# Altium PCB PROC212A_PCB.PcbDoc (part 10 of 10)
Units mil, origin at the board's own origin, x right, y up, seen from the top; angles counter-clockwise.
Board outline 3032.48 x 3598.78 mil, 4 copper layers (Top Layer, L2_GND1, L3_PWR1, Bottom Layer), stack 60.58 mil thick; 432 components, 310 nets, 7775 pads, 1236 vias.
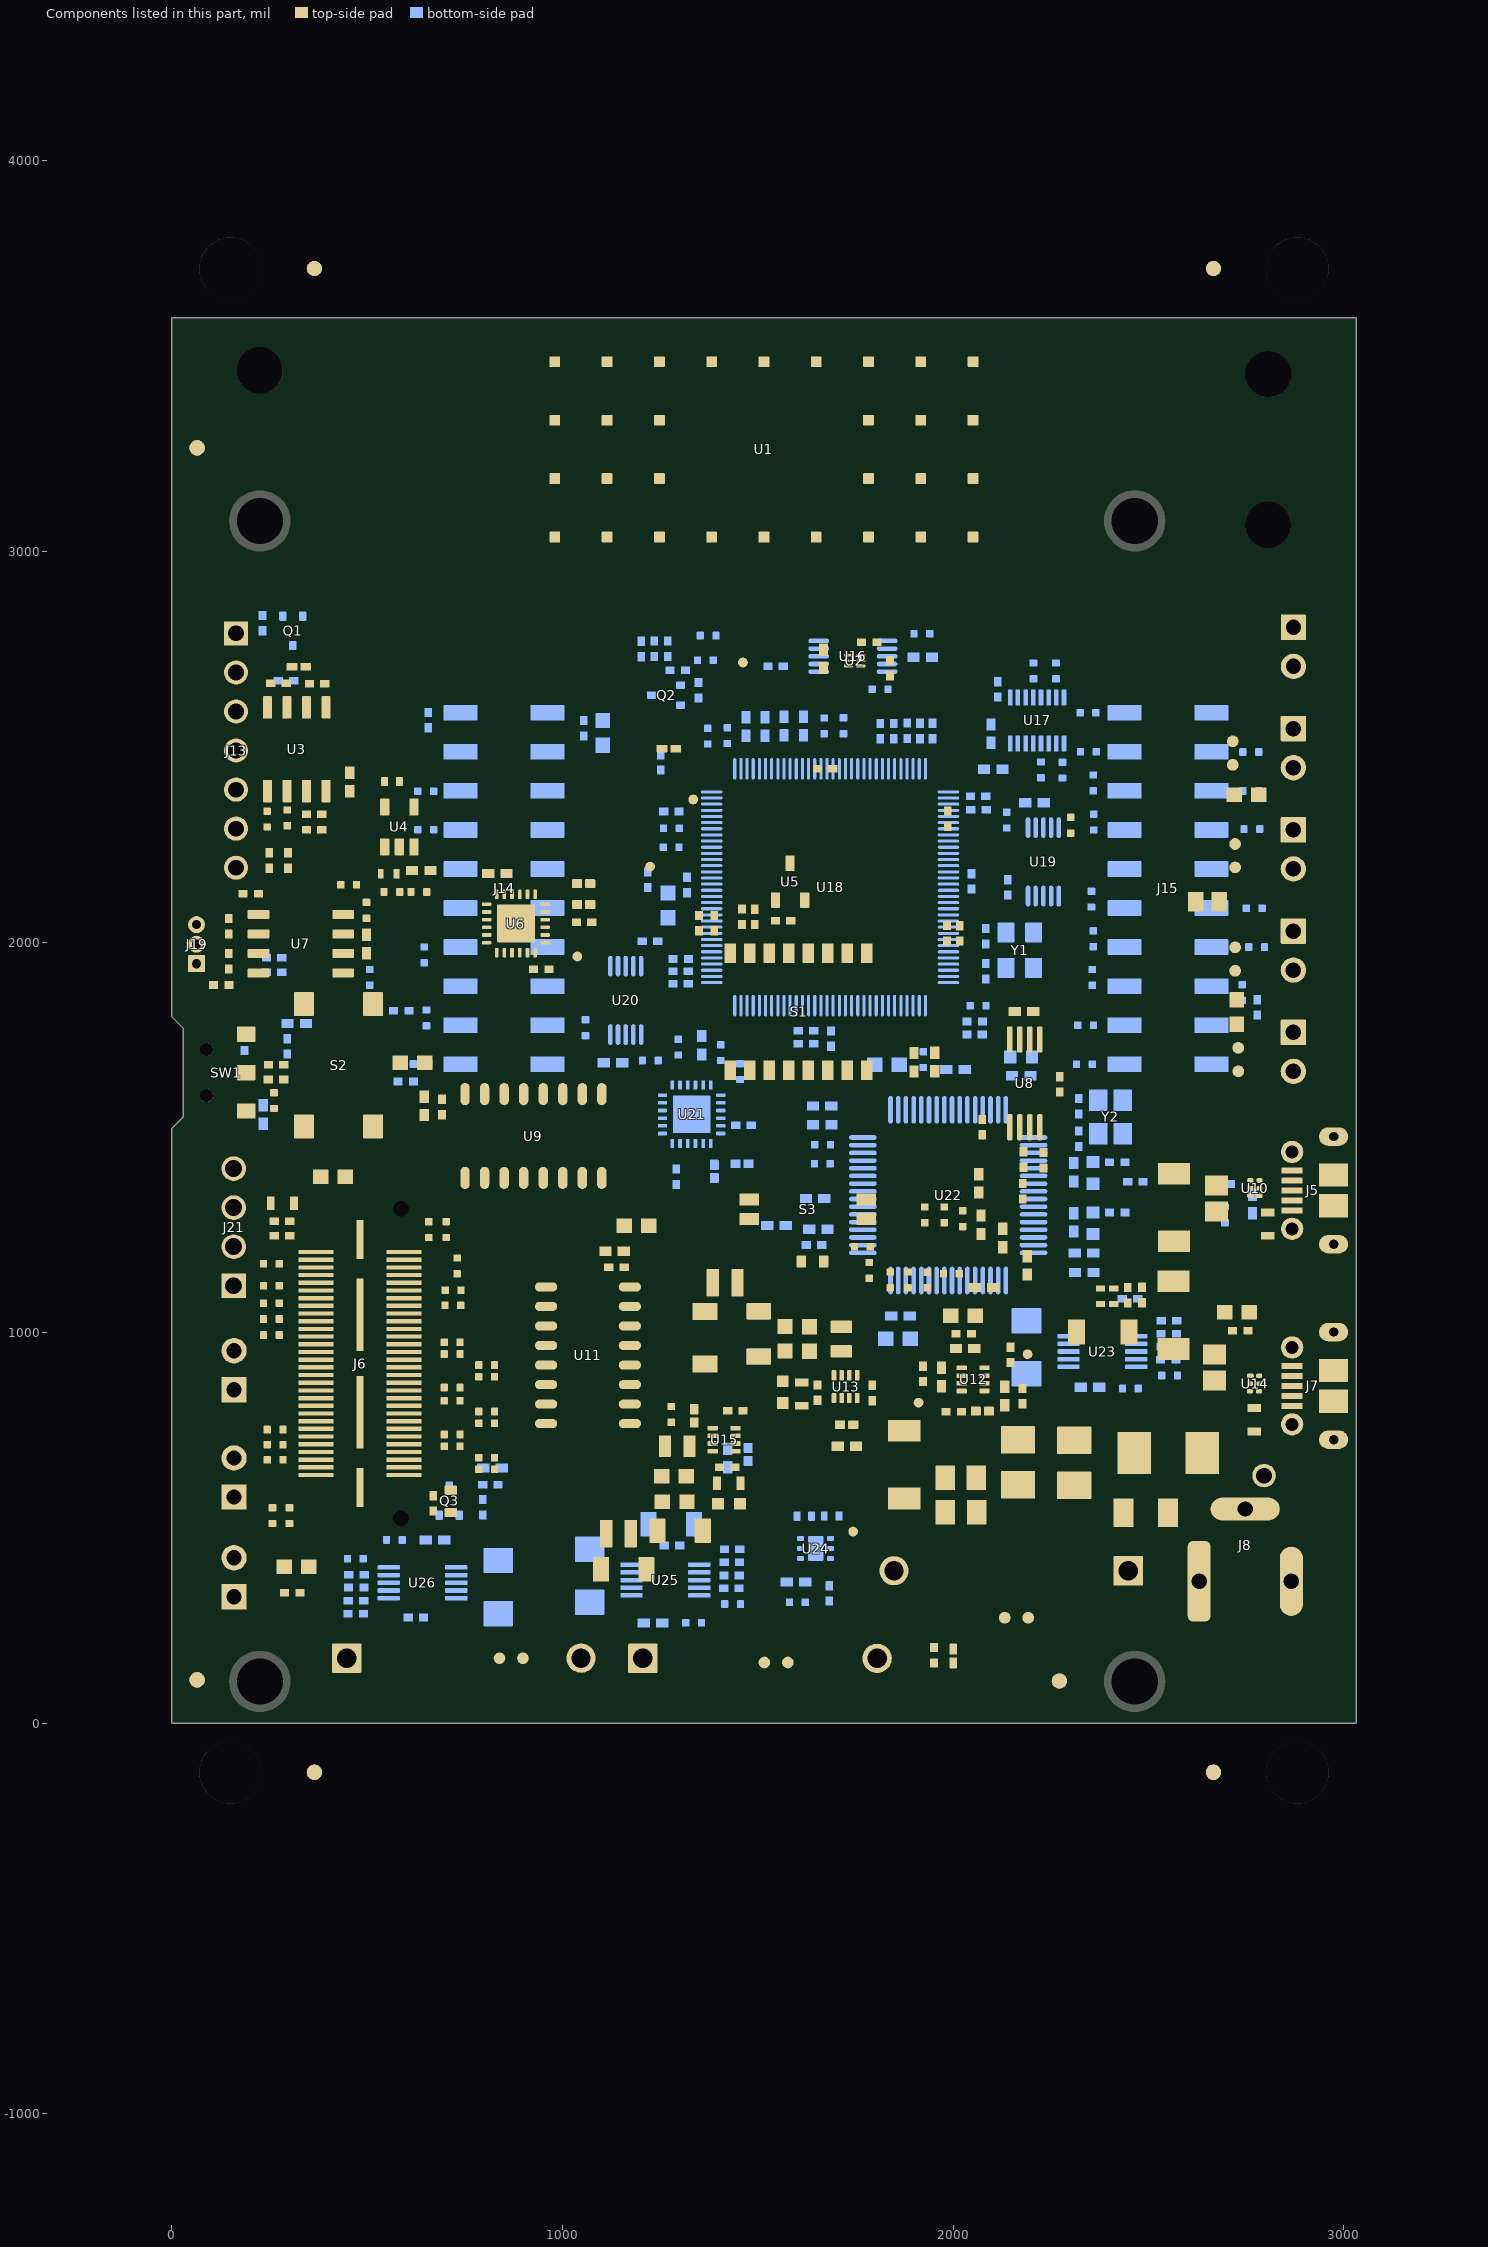
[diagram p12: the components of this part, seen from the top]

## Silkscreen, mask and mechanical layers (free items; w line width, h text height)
Top Overlay:
  circle w15: c1435.74,1342.41 r1
  circle w15: c1518.68,2068.65 r1
  circle w15: c2796.02,1333.86 r1
  circle w15: c2742.02,900.86 r1
  circle w15: c1783.02,2679.86 r1
  circle w15: c946.02,1161.86 r1
  circle w15: c706.02,1403.86 r1
  circle w15: c441.02,2599.86 r1
  circle w15: c555.14,1887.52 r3.1
  circle w1.51: c2325.05,2100.75 r4.71
  circle w1.51: c2325.05,2100.75 r4.71
  lines w0.38: 2318.02,2094.77 2273.52,2079.71 2318.02,2094.77 ; 2318.02,2094.77 2276.32,2074.11 2318.02,2094.77
  lines w0.76: 2315.22,2093.56 2310.14,2091.82 2315.22,2093.56 ; 2315.22,2093.56 2309.84,2091.14 2315.22,2093.56
  lines w1.51: 2309.84,2091.37 2274.5,2079.34 2309.84,2091.37 ; 2309.84,2091.37 2275.94,2074.87 2309.84,2091.37
  lines w3.03: 2280.03,2078.12 2277,2079.18 2280.03,2078.12 ; 2280.03,2078.12 2273.14,2075.63 2280.03,2078.12 ; 2202.83,2107.64 2207,2109.76 2202.83,2107.64 ; 2275.79,2077.44 2297.89,2086.37 2275.79,2077.44
  lines w6.81: 2174.23,2082.06 2178.39,2086.3 ; 2174.23,2082.06 2178.39,2086.3 ; 2174.23,2082.06 2167.87,2075.02 2174.23,2082.06 ; 2178.39,2086.3 2182.17,2089.93 ; 2178.39,2086.3 2182.17,2089.93 ; 2182.17,2089.93 2184.14,2091.82 ; 2182.17,2089.93 2184.14,2091.82 ; 2184.14,2091.82 2188.68,2095.45 ; 2184.14,2091.82 2188.68,2095.45 ; 2188.68,2095.45 2192.92,2098.94 ; 2188.68,2095.45 2192.92,2098.94 ; 2192.92,2098.94 2194.59,2100.07 ; 2192.92,2098.94 2194.59,2100.07 ; 2194.59,2100.07 2196.55,2101.28 ; 2194.59,2100.07 2196.55,2101.28 ; 2196.55,2101.28 2199.66,2103.25 2196.55,2101.28 ; 2203.59,2105.97 2196.25,2101.28 2203.59,2105.97 ; 2203.59,2105.97 2195.95,2101.21 2203.59,2105.97 ; 2209.04,2082.74 ccw(c2213.22,2079.56) 2216.53,2075.48 ; 2209.04,2082.74 ccw(c2213.22,2079.56) 2216.53,2075.48 ; 2209.04,2082.74 2223.8,2102.11 ; 2209.04,2082.74 2223.8,2102.11 ; 2212.29,2110.21 2216.15,2111.8 ; 2212.29,2110.21 2216.15,2111.8 ; 2212.29,2110.21 2207.3,2107.79 2212.29,2110.21 ; 2216.15,2111.8 cw(c2219.57,2104.52) 2223.57,2111.5 ; 2216.15,2111.8 cw(c2219.57,2104.52) 2223.57,2111.5 ; 2216.53,2075.48 cw(c2325.44,1885.68) 2261.41,2094.92 ; 2216.53,2075.48 cw(c2325.44,1885.68) 2261.41,2094.92 ; 2223.57,2111.5 cw(c2221.9,2108.59) 2225.16,2109.38 ; 2223.57,2111.5 cw(c2221.9,2108.59) 2225.16,2109.38 ; 2223.8,2102.11 ccw(c2216.39,2107.26) 2225.16,2109.38 ; 2223.8,2102.11 ccw(c2216.39,2107.26) 2225.16,2109.38 ; 2261.41,2094.92 cw(c2262.16,2089.46) 2267.54,2090.69 ; 2261.41,2094.92 cw(c2262.16,2089.46) 2267.54,2090.69 ; 2267.54,2090.69 cw(c2246.21,2085.81) 2267.77,2082.06 ; 2267.54,2090.69 cw(c2246.21,2085.81) 2267.77,2082.06 ; 2267.77,2082.06 ccw(c2272.69,2081.2) 2274.27,2076.46 cw(c2272.69,2081.2) 2267.77,2082.06 ; 2198.45,2102.42 2201.25,2104.31 2198.45,2102.42 ; 2199.88,2103.63 2205.26,2106.58 2199.88,2103.63
  lines w10: 2654.31,1702.09 2584.31,1702.09 2584.31,1943.09 2654.31,1943.09 ; 2654.31,1960.09 2584.31,1960.09 2584.31,2214.09 2654.31,2214.09 ; 2655.31,2231.09 2585.31,2231.09 2585.31,2483.09 2655.31,2483.09 ; 2900.09,2237.09 2970.09,2237.09 2970.09,2482.09 ; 2900.09,2483.09 2968.09,2483.09 ; 2901.09,1982.09 2971.09,1982.09 2971.09,2219.09 ; 2901.09,2220.09 2969.09,2220.09 ; 2901.31,1964.09 2971.31,1964.09 2971.31,1694.09 2909.31,1694.09
  text "RESET_LED" at 306.31,2746.09 h30
  text "PMIC_CLK_OUT" at 1149.02,2699.86 h25
  text "PROC212 REV. A" at 607.02,2633.86 h60
  text "VCC_MOD_3V3" at 2601.31,2548.09 h20
  text "PRESENCE_LED" at 854.02,2478.86 h30
  text "TEXAS" at 1450.6,2428.69 h25
  text "INSTRUMENTS" at 1405.15,2385.87 h25
  text "XDS_UART_RX" at 1255.69,2317.03 h20
  text "VCC_MOD" at 2953.31,2282.09 h25 r90
  text "XDS_UART_TX" at 1280.79,2194.46 h20
  text "R" at 2323.57,2098.67 h4.54
  text "7. FTDI_RS232" at 1683.77,2031.9 h20 r90
  text "6. FTDI_SPI" at 1714.94,2031.9 h20 r90
  text "5. XDS_RS232" at 1745.29,2031.9 h20 r90
  text "4. XDS_JTAG" at 1775.64,2031.9 h20 r90
  text "3. I2C" at 1808.44,2031.9 h20 r90
  text "2. LVDS" at 1842.07,2031.9 h20 r90
  text "1. FLASH/FUNCT MODE" at 1878.72,2031.9 h20 r90
  text "MISTRAL" at 2147.7,2018.27 h41.62
  text "VCC_1V8" at 2953.31,2015.09 h25 r90
  text "HOST_CLK_REQ" at 1026.33,1916.65 h20
  text "Func_MODE" at 50.89,1822.6 h27
  text "RESET_SW" at 567.31,1790.09 h30
  text "MUX_CTRL" at 1310.38,1736.41 h20 r90
  text "VCC_IO_MOD" at 2953.31,1713.09 h25 r90
  text "to be closed for Module power-up." at 2533.31,1634.09 h25 r90
  text "VCC_MODULE and VCC_IO_MOD jumpers/solder blobs" at 2475.31,1633.09 h25 r90
  text "VCC_IO_3V3" at 2629.31,1614.09 h20
  text "FTDI USB" at 2778.31,1545.09 h30
  text "Flash MODE" at 45.85,1489.23 h27
  text "SOP0 Switch" at 41.77,1453.57 h27
  text "DCA_LP_JTAG" at 1641.17,1415.02 h20 r90
  text "DCA_LP_SPI/" at 1530.18,1412.98 h20 r90
  text "CAN_FD_RX" at 1561.75,1412.98 h20 r90
  text "DEBUG MODE" at 1801.39,1412.05 h20 r90
  text "DCA_FTDI_SPI" at 1689.71,1409.55 h20 r90
  text "MOD_WU,GPIO/" at 1730.35,1407.12 h20 r90
  text "CAN_FD_TX" at 1766.35,1407.12 h20 r90
  text "FT_DCA_RS232" at 1594.68,1404.77 h20 r90
  text "DCA_LP_RS232" at 1488.02,1402.71 h20 r90
  text "I2C_SWITCH" at 1390.1,1212.7 h20 r90
  text "FTDI" at 1601,1128.84 h20
  text "XDS110 USB" at 2719.31,1098.09 h30
  text "SUSPEND" at 1565.48,1097.09 h20
  text "GND" at 2838.31,614.09 h30
  text "VCC_3V3" at 1644.02,515.86 h25
  text "P_GOOD" at 759.9,485.9 h20
  text "VCC_5V curr meas point" at 1862.31,452.09 h25
  text "DCA_CONN" at 499.96,447.49 h25
  text "VCC_5V" at 1970.8,311.96 h25
  text "3V3_MODULE curr meas point" at 1226.31,274.09 h25
  text "3V3_IO curr meas point" at 510.31,271.09 h25
  text "5V_SNS" at 2231.31,255.09 h25
  text "DC Jack" at 2757.31,129.09 h30
  text "5V_LED" at 1926.31,96.09 h25
  text "VCC_IO_3V3" at 877.31,67.09 h25
  text "3V3_MODULE_SNS" at 1152.31,67.09 h25
  text "VCC_MOD_3V3" at 1568.31,67.09 h25
  text "3V3_IO_SNS" at 585.31,65.09 h25
  text ".Layer_Name" at -379.69,-686.91 h60
Bottom Overlay:
  circle w10: c2483.02,1602.86 r3.16
  circle w10: c1712.02,478.86 r3.16
  circle w15: c1640.1,2653.48 r3.1
  circle w15: c1106.09,1979.63 r3.1
  circle w15: c2143.74,2668.12 r3.1
  circle w15: c2309.05,2115.36 r3.1
  circle w15: c1196.15,2629.78 r3.1
  rectangle: 550.57,1016.4 1239,1114.63
  lines w6: 2811.31,2130.09 2811.31,2152.09 2826.31,2167.09 ; 2812.31,1829.09 2812.31,1811.09 2826.31,1797.09 ; 2813.31,2344.09 2813.31,2326.09 2827.31,2312.09 ; 2814.4,2093.91 2814.4,2075.91 2828.4,2061.91 ; 2816.31,2390.09 2816.31,2412.09 2831.31,2427.09 ; 2819.76,1871.34 2819.76,1893.34 2834.76,1908.34
  lines w10: 550.57,1116.54 1376.75,1116.54 ; 550.57,1116.68 550.57,1016.54 1376.75,1016.54 1376.75,1116.68 ; 1238.45,1016.4 1238.45,1114.63
  text "SPI_CONN" at 198.31,2907.09 h25
  text "GND" at 2814.02,2784.86 h20
  text "LP/BP_CONN" at 2671.18,2705.83 h25
  text "GND" at 2816.02,2698.86 h20
  text "MOSI" at 307.18,2697.09 h25
  text "LP/BP_CONN" at 957.02,2697.15 h25
  text "3V3" at 720.31,2633.09 h35
  text "5V" at 1021.31,2633.09 h35
  text "GND" at 2748.22,2627.02 h35
  text "MISO" at 311.35,2568.09 h25
  text "3V3_MOD" at 2830.22,2533.28 h20
  text "CS" at 265.53,2475.09 h25
  text "CLK" at 290.52,2374.2 h25
  text "VCC_MOD" at 2937.14,2359.93 h20
  text "HOST_INTR" at 436.31,2269.09 h25
  text "GND" at 290.52,2170.2 h25
  text "VCC_1V8" at 2944.31,2102.09 h20
  text "CAN_HEADER" at 392.84,2083.73 h25
  text "CANL" at 194.04,2032.61 h25
  text "GND" at 177.24,1981.01 h25
  text "CANH" at 198.44,1929.41 h25
  text "VCC_MOD_IO" at 2991.52,1842.8 h20
  text "3V3_IO_PWR" at 2899.31,1594.09 h20
  text "GND" at 258.64,1405.37 h20
  text "TX" at 236.54,1308.13 h20
  text "RS232_CONN" at 498.34,1270.22 h25
  text "RX" at 244.28,1210.9 h20
  text "FY25-26/00546000101" at 1274.31,1159.09 h28
  text "VCC_IO_MOD" at 395.65,1108.14 h20
  text "SL#" at 1365.15,1038.2 h70
  text "MCU_5V_HDR" at 414.08,831.33 h20
  text "GND" at 2919.63,610.28 h30
  text "VPP_LDO" at 359.65,604.45 h20
  text "MCU_3V3" at 288.59,463.77 h20
  text ".Layer_Name" at -426.69,-683.91 h60
Top Paste:
  text ".Layer_Name" at -544.88,-674.55 h60
Bottom Paste:
  text ".Layer_Name" at -544.88,-674.55 h60
Top Solder:
  text ".Layer_Name" at -374.69,-678.91 h60
  text ".Layer_Name" at -397.69,-681.91 h60
Bottom Solder:
  text ".Layer_Name" at -404.69,-686.91 h60
Drill Guide:
  text ".Layer_Name" at 213.27,-699.88 h60
M1 Board Outline:
  lines w6: 0.02,-0.02 0.02,-275.73 3032.46,-275.73 3032.46,0 ; 0,3598.78 3032.51,3598.78 ; 0,3598.78 0,3874.51 3032.51,3874.51 3032.51,3598.78 ; 0,3598.78 0,1808.43 29.41,1779.02 29.41,1552.81 0,1523.4 0,0 3032.46,0 ; 3032.48,0 3032.48,3598.78 ; 3031.47,1559.07 3031.49,1559.07
  text ".Layer_Name" at -480.55,-740.88 h40
M3 3D STEP Top:
  text ".Layer_Name" at -544.88,-674.55 h60
M4 3D STEP Bottom:
  text ".Layer_Name" at -544.88,-674.55 h60
M5 Assembly Top:
  circle w6: c2718.02,2482.86 r60
  circle w6: c2721.39,2217.76 r60
  circle w6: c2723.78,1953.96 r60
  circle w6: c2730.36,1697.34 r60
  circle w6: c870.44,164.1 r60
  circle w6: c1549.02,155.86 r60
  circle w6: c2162.02,268.86 r60
  circle w6: c2796.2,634.06 r39.69
  circle w6: c1744.12,490.77 r18.56
  circle w6: c1911.68,820.76 r18.56
  circle w6: c2190.81,944.83 r18.56
  circle w6: c1462.02,2715.86 r18.56
  circle w6: c1334.73,2365.09 r18.56
  circle w6: c1224.1,2193.24 r18.56
  circle w6: c1038.08,1963.33 r18.56
  lines w10: -1386.45,-990.71 5213.55,-990.71 ; -1386.45,-787.38 5215.55,-787.38 ; -1386.45,-584.04 -1386.45,-1194.04 2618.55,-1194.04 5215.55,-1194.04 5215.55,-584.04 -1385.95,-584.04 -1385.95,-1194.04 189.55,-1194.04 ; 1078.55,-1194.04 1078.55,-584.04 ; 2345.55,-787.38 2345.55,-584.04 ; 3185.55,-787.38 3185.55,-584.04 ; 3807.55,-1200.54 3807.55,-997.71
  text "COMPONENTS MARKED 'DNP' SHOULD NOT BE POPULATED." at -689.69,4171.09 h60
  text "ASSEMBLY VARIANT:" at -221.21,4053.92 h60
  text ".VariantName" at 814.79,4053.92 h60
  text "TP1" at 1492.29,2709.08 h24
  text "J1" at 2594.21,2495.66 h24
  text "TP2" at 1365.01,2358.31 h24
  text "J2" at 2605.91,2250.38 h24
  text "TP3" at 1203.15,2222.38 h24
  text "J3" at 2596.91,1975.38 h24
  text "TP4" at 1068.35,1956.55 h20
  text "J4" at 2602.91,1666.38 h24
  text "TP5" at 2220.09,937.05 h14
  text "TP6" at 1882.5,807.76 h16 r90
  text "TP7" at 2851.24,653.63 h20
  text "TP8" at 1774.39,483.99 h24
  text "J11" at 1523.94,235.61 h24
  text "J10" at 923.14,230.22 h24
  text "J9" at 2144.91,152.37 h24
  text "PCB VIEWED FROM TOP SIDE" at -1280.46,-526.57 h60
  text "BOARD #:" at 1196.04,-526.57 h60
  text ".PRJ_Number" at 1741.54,-526.57 h60
  text "REV:" at 2586.04,-526.57 h60
  text ".PCB_Rev" at 2877.54,-526.57 h60
  text "SVN REV:" at 3424.04,-526.57 h60
  text ".VersionControl_RevNumber" at 3930.04,-526.57 h60
  text "Assembly Layer Top" at -513.95,-667.54 h60
  text "TID #:" at 1196.04,-729.91 h60
  text ".TID" at 1741.54,-729.91 h60
  text "PLOT NAME =" at -1280.46,-935.24 h60
  text ".plot_File_Name" at -474.96,-935.24 h60
  text ".Print_Date" at 2067.54,-935.24 h60
  text ".Print_Time" at 2796.54,-935.24 h60
  text "TEXAS INSTRUMENTS" at 4061.04,-935.24 h60
  text "GENERATED    :" at 1201.02,-936.14 h60
M6 Assembly Bottom:
  circle w4: c1437.91,2242.94 r15
  lines w10: -1384.46,-788.24 5217.54,-788.24 ; -1382.46,-991.57 5217.54,-991.57 ; 23.54,-1201.41 23.54,-998.57 ; 645.54,-788.24 645.54,-584.91 ; 1485.54,-788.24 1485.54,-584.91 ; 2752.54,-1194.91 2752.54,-584.91 ; 3641.54,-1194.91 5217.04,-1194.91 5217.04,-584.91 -1384.46,-584.91 -1384.46,-1194.91 1212.54,-1194.91 5217.54,-1194.91 5217.54,-584.91
  text "COMPONENTS MARKED 'DNP' SHOULD NOT BE POPULATED." at 5201.02,-357.14 h60
  text ".VariantName" at 4170.61,-477.86 h60
  text "ASSEMBLY VARIANT:" at 5209.61,-477.86 h60
  text ".VersionControl_RevNumber" at -56.46,-717.07 h60
  text "SVN REV:" at 449.54,-717.07 h60
  text ".PCB_Rev" at 996.04,-717.07 h60
  text "REV:" at 1287.54,-717.07 h60
  text ".PRJ_Number" at 2132.04,-717.07 h60
  text "BOARD #:" at 2677.54,-717.07 h60
  text "PCB VIEWED FROM BOTTOM SIDE" at 5154.04,-717.07 h60
  text "Assembly Bottom Layer" at 4793.04,-905.91 h60
  text ".TID" at 2132.04,-920.41 h60
  text "TID #:" at 2677.54,-920.41 h60
  text "GENERATED    :" at 2708.02,-1116.91 h60
  text "TEXAS INSTRUMENTS" at -187.46,-1125.74 h60
  text ".Print_Time" at 1077.04,-1125.74 h60
  text ".Print_Date" at 1806.04,-1125.74 h60
  text ".plot_File_Name" at 4348.54,-1125.74 h60
  text "PLOT NAME =" at 5154.04,-1125.74 h60
M10 Fab Notes:
  drawing of 356 lines, arcs and shapes, not listed
  text "1" at -312.13,8207.59 h70
  text "2" at 2183.54,8207.59 h70
  text "3" at 4672.88,8207.59 h70
  text "4" at 7179.55,8207.59 h70
  text "5" at 9678.54,8207.59 h70
  text "6" at 12183.54,8207.59 h70
  text "A" at -1468.46,7064.59 h70
  text "A" at 13331.54,7064.59 h70
  text "DESIGN INFORMATION" at 11330.05,6527.27 h60
  text "4.0" at 11724.53,6397.87 h60
  text "MIN. TRACK WIDTH:" at 10685.49,6395.14 h60
  text "MIL" at 11936.49,6395.14 h60
  text "4.5" at 11721.99,6278.49 h60
  text "MIN. CLEARANCE:" at 10685.49,6271.02 h60
  text "MIL" at 11936.49,6271.02 h60
  text "MIN. VIA PAD SIZE:" at 10685.49,6146.89 h60
  text "18" at 11708.18,6139.52 h60
  text "MIL" at 11959.04,6138.09 h60
  text "EXTERNAL" at 12206.64,6019.58 h60
  text "0.127mm (5.0MIL)" at 11380.5,6016.99 h60
  text "MINIMUM ANNULAR RING" at 10356.26,6008.77 h60
  text "PER" at 10556.26,5898.64 h60
  text "IPC-D-275 CLASS 2 LEVEL C" at 10776.26,5898.64 h60
  text "45" at 7428.01,5823.91 h80
  text "MIL, HOLES" at 12264.49,5798.16 h60
  text "+/-" at 11872.04,5789.58 h60
  text "+/-" at 12726.04,5789.58 h60
  text "REGISTRATION TOLERANCES:" at 10356.26,5788.51 h60
  text "METAL" at 11556.04,5788.51 h60
  text "2" at 12132.24,5788.52 h60
  text "3" at 12965.24,5788.52 h60
  text "MIL" at 13081.49,5788.51 h60
  text "HOLE SIZE TOLERANCE (UNLESS OTHERWISE SPECIFIED):" at 10356.26,5690.2 h60
  text "+/-" at 12726.04,5687.32 h60
  text "3" at 12965.24,5686.26 h60
  text "MIL" at 13081.49,5686.26 h60
  text "TYP" at 7388.01,5658.91 h80
  text "MATERIAL:" at 10281.5,5548.61 h60
  text "0.55MM" at 6347.59,5445.58 h80
  text "FR-4 High Tg" at 11267.94,5420.09 h60
  text "X" at 11122.02,5412.86 h60
  text "FR-408" at 10702.5,5407.58 h60
  text "OTHER" at 12190.5,5407.58 h60
  text "62 MIL (1.6mm) +/-10%" at 11022.6,5264.55 h60
  text "X" at 10894.7,5262.2 h60
  text "THICKNESS:" at 10356.26,5256.33 h60
  text "OTHER" at 12307.5,5256.33 h60
  text "TOLERANCE:" at 10356.26,5118.02 h60
  text "X" at 11204.5,5118.02 h60
  text "ANSI IPC-6012 TYPE 3 CLASS 2" at 11382.51,5118.02 h60
  text "1.6MM" at 5717.59,4980.58 h80
  text "0.50MM" at 8565.51,4980.58 h80
  text "OTHER +/-" at 11382.5,4973.83 h60
  text "BOW & TWIST:" at 10356.26,4828.64 h60
  text "X" at 11204.5,4828.64 h60
  text "ANSI IPC-6012 TYPE 3 CLASS 2" at 11382.51,4828.64 h60
  text "B" at -1468.46,4684.59 h70
  text "B" at 13331.54,4684.59 h70
  text "OTHER +/-" at 11382.5,4681.94 h60
  text "DRILLING:" at 10281.5,4551.32 h60
  text "NC_DRILL FILES" at 12042.49,4446.13 h60
  text "REFERENCE:" at 10356.26,4442.2 h60
  text "X" at 11013.5,4442.1 h60
  text "AS SHOWN" at 11191.49,4442.2 h60
  text "X" at 11914.5,4442.2 h60
  text "0.10MM" at 6937.59,4401.41 h80
  text "OTHER" at 12340.5,4299.95 h60
  text "PTH COPPER THICKNESS:" at 10355.94,4296.42 h60
  text "X" at 11495.18,4296.42 h60
  text "20-30 um" at 11623.17,4296.42 h60
  text "DETAIL-A(V-GROOVE DETAILS)" at 6420.09,4239.28 h80
  text "REFER DETAIL-A" at 2491.32,4193.05 h40
  text "BOARD FINISH:" at 10281.5,4148.82 h60
  text "SCALE : NTS" at 6932.27,4098.72 h80
  text "SILKSCREEN:" at 10436.72,4038.69 h60
  text "X" at 11394.5,4038.69 h60
  text "TOP" at 11511.49,4038.69 h60
  text "X" at 11904.5,4038.69 h60
  text "BOTTOM" at 12022.49,4038.69 h60
  text "NOTES : UNLESS OTHERWISE SPECIFIED." at 3738.75,3954.17 h60
  text "SILKSCREEN COLOR:" at 10436.72,3883.5 h60
  text "X" at 11393.5,3883.5 h60
  text "WHITE" at 11511.49,3883.5 h60
  text "OTHER" at 12022.49,3883.5 h60
  text "1. ALL VIAS ARE TENTED ON BOTH SIDES UNLESS SOLDERMASK OPENED IN GERBER." at 3909.44,3756.46 h60
  text "GREEN" at 11642.49,3740.06 h60
  text "X" at 12116.5,3740.06 h60
  text "OTHER" at 12260.5,3740.06 h60
  text "RED" at 12633.03,3740.06 h60
  text "SOLDER RESIST COLOR:" at 10436.72,3733.19 h60
  text "2. ALL VIAS SHOULD BE FILLED WITH NON CONDUCTIVE EPOXY AND SURFACE SHOULD BE FLAT." at 3909.44,3656.46 h60
  text "MATTE" at 11642.49,3585.8 h60
  text "SEMI-GLOSS" at 12260.04,3585.17 h60
  text "X" at 12106.72,3582.15 h60
  text "3. MANUFACTURER'S IDENTIFICATION, DATECODE LETTER SHALL BE SILKSCREENED ON SOLDER SIDE" at 3909.44,3548.63 h60
  text "OF THE BOARD." at 4026.9,3434.83 h60
  text "IMMERSION GOLD (ENIG)" at 11342.49,3413.03 h60
  text "X" at 11164,3410.98 h60
  text "ENEPIG" at 12680.04,3405.81 h60
  text "SURFACE FINISH:" at 10281.5,3404.81 h60
  text "4. BOARD DIMENSIONS ARE IN MM." at 3909.44,3327.86 h60
  text "IMM. TIN/SILVER OR EQUIV" at 10611.04,3267.5 h60
  text "OTHER" at 12042.5,3263.56 h60
  text "5. TEAR DROPS SHALL BE ADDED ON INTERNAL AND EXTERNAL LAYER FOR ALL THE VIA'S AND THROUGH HOLE PADS." at 3909.44,3193.94 h60
  text "ARRAY/PANEL:" at 10281.5,3108.18 h60
  text "CUT AND TRIM PER M1 BOARD OUTLINE" at 11342.5,3099.96 h60
  text "6. ALL UNCONNECTED VIA'S SHALL BE SUPPRESSED." at 3917.23,3081.08 h60
  text "N.C. ROUTE" at 11342.49,2963.99 h60
  text "V. SCORE" at 12208.5,2963.99 h60
  text "X" at 12025.49,2958.05 h60
  text "CERTIFICATION:" at 10281.5,2834.87 h60
  text "MATERIALS AND WORKMANSHIP FOR ALL PCBS" at 11006.5,2834.87 h60
  text "TO MEET OR EXCEED THE REQUIREMENTS OF:" at 11006.5,2740.8 h60
  text "X" at 10644,2612.17 h60
  text "ANSI IPC-A-600F CLASS ->" at 10772,2612.17 h60
  text "X" at 12420,2612.17 h60
  text "2" at 12530,2612.17 h60
  text "1" at 12215,2610.68 h60
  text "3" at 12884,2610.68 h60
  text "C" at -1468.46,2534.59 h70
  text "X" at 11456,2464.49 h60
  text "RoHS" at 11584,2464.49 h60
  text "OTHER" at 12228.4,2464.49 h60
  text "PER ORDER" at 12625.46,2464.49 h60
  text "ALL BOARDS MUST MEET OR EXCEED UL94-V0 REQUIREMENTS." at 10309.04,2310.66 h60
  text "C" at 13331.54,2309.59 h70
  text "PCB MUST BEAR THE UL94V-0 UL REGISTERED MATERIAL ID NUMBER" at 10309.04,2194.6 h60
  text "ADDITIONAL REQUIREMENTS:" at 10281.5,2025.17 h60
  text "MICROSECTION:" at 10356.26,1918.05 h60
  text "YES" at 11262,1918.05 h60
  text "REQUIRED" at 12123.49,1773.71 h60
  text "BARE BOARD ELEC. TEST:" at 10356.26,1770.86 h60
  text "NONE" at 11662,1770.86 h60
  text "X" at 12005.5,1770.86 h60
  text "PER ORDER" at 12715.5,1770.86 h60
  text "ALL VIAS REQUIRE NON-CONDUCTIVE FILL AND PLANARIZE" at 10476.42,1567.74 h59
  text "XX MIL VIAS REQUIRE CONDUCTIVE FILL AND PLANARIZE" at 10541.47,1477.58 h60
  text "BOARD IMPEDANCE SHALL BE FOLLOWED AS PER THE" at 10540.49,1314.19 h56
  text "X" at 10420.42,1297.34 h60
  text "IMPEDANCE SPECIFICATION TABLE." at 10540.83,1216.2 h56
  text "PROJECT TITLE:" at 10291.54,448.59 h45
  text ".PRJ_Title" at 10341.54,315.27 h70
  text "D" at -1468.46,164.59 h70
  text "DESIGNED FOR:" at 10291.54,147.59 h45
  text "REFER DETAIL-A" at 3279.35,39.59 h40
  text ".PRJ_Customer" at 10341.54,7.59 h70
  text "D" at 13331.54,-60.41 h70
  text "FILE NAME:" at 10291.54,-152.41 h45
  text ".PCB_File_Name_No_Path" at 10341.54,-272.41 h70
  text "Texas Instruments (TI) and/or its licensors do not warrant the accuracy or completeness of this specification" at 5322.04,-434.24 h45
  text "ENGINEER:" at 10291.54,-442.41 h45
  text "LAYOUT BY:" at 11796.54,-442.41 h45
  text "or any information contained therein. TI and/or its licensors do not warrant that this design will meet" at 5277.05,-546.91 h45
  text ".PRJ_Engineer" at 10341.54,-597.4 h70
  text ".PCB_Layout" at 11847.04,-597.4 h70
  text "the specifications, will be suitable for your application or fit for any particular purpose, or will operate in" at 5277.05,-659.58 h45
  text "ALTIUM DESIGNER VERSION:" at 11796.54,-752.41 h45
  text "an implementation. TI and/or its licensors do not warrant that the design is production worthy. You should" at 5277.05,-772.24 h45
  text "completely validate and test your design implementation to confirm the system functionality for your application." at 5322.04,-884.91 h45
  text ".print_Scale" at 10341.54,-885.73 h70
  text ".Application_BuildNumber" at 11847.04,-885.73 h70
  text "4" at 7179.55,-1089.41 h70
  text "5" at 9678.54,-1089.41 h70
  text "1" at -312.13,-1092.41 h70
  text "2" at 2183.54,-1092.41 h70
  text "3" at 4672.88,-1092.41 h70
  text "6" at 12032.72,-1102.76 h70
M11 Gerber Information:
  lines w10: -1343.96,-962.41 2661.04,-962.41 5258.04,-962.41 5258.04,-352.41 -1343.46,-352.41 -1343.46,-962.41 232.04,-962.41 ; -1343.96,-759.07 5256.04,-759.07 ; -1343.96,-555.74 5258.04,-555.74 ; 1121.04,-962.41 1121.04,-352.41 ; 2388.04,-555.74 2388.04,-352.41 ; 3228.04,-555.74 3228.04,-352.41 ; 3850.04,-968.91 3850.04,-766.07
  text "SVN REV:" at 3424.04,-464.57 h60
  text ".VersionControl_RevNumber" at 3930.04,-464.57 h60
  text "ALL ARTWORK VIEWED FROM TOP SIDE" at -1280.46,-484.57 h60
  text "BOARD #:" at 1196.04,-484.57 h60
  text ".PRJ_Number" at 1741.54,-484.57 h60
  text "REV:" at 2586.04,-484.57 h60
  text ".PCB_Rev" at 2877.54,-484.57 h60
  text ".Layer_Name" at -530.26,-663.7 h60
  text "LAYER NAME =" at -1280.46,-687.4 h60
  text "TID #:" at 1196.04,-687.91 h60
  text ".TID" at 1741.54,-687.91 h60
  text "PLOT NAME =" at -1280.46,-893.24 h60
  text ".plot_File_Name" at -474.96,-893.24 h60
  text "GENERATED    :" at 1198.04,-893.24 h60
  text ".Print_Date" at 2067.54,-893.24 h60
  text ".Print_Time" at 2796.54,-893.24 h60
  text "TEXAS INSTRUMENTS" at 4061.04,-893.24 h60
M12 Stackup:
  drawing of 391 lines, arcs and shapes, not listed
  text "IMPEDANCE TABLE" at 7259.51,7454.37 h80
  text "LAYER" at 6578.79,7270.37 h70
  text "TRACE WIDTH" at 6865.99,7269.53 h70
  text "SPACING" at 7350.99,7269.53 h70
  text "IMPEDANCE +/- 10%" at 7685.99,7269.53 h70
  text "REFERENCE LAYER" at 8410.99,7269.53 h70
  text "4.5 MILS" at 6971.99,7097.18 h65
  text "LAYER-2" at 8550.53,7093.48 h65
  text "4.5 MILS" at 7372.9,7089.45 h65
  text "90 OHM" at 7846.02,7088.4 h65
  text "TOP" at 6552.32,7074.84 h70
  text "4.5 MILS" at 6966.95,6918.53 h65
  text "LAYER-3" at 8558.95,6917.17 h65
  text "4.5 MILS" at 7383.88,6911.63 h65
  text "BOTTOM" at 6561.43,6898.45 h60
  text "90 OHM" at 7854.37,6890.44 h65
  text "TOP /" at 6577.39,6762.8 h70
  text "LAYER-2" at 8399.67,6731.83 h65
  text "/ LAYER-3" at 8664.74,6729.62 h65
  text "-" at 7467.94,6727.21 h65
  text "50 OHM" at 7857.4,6722.96 h65
  text "5.9 MILS" at 6967.6,6719.46 h65
  text "BOTTOM" at 6533.5,6695.39 h60
  text "TOP" at 6597.97,6545.7 h70
  text "LAYER-2" at 8558.95,6539.47 h65
  text "4 MILS" at 6957.77,6535.69 h65
  text "6 MILS" at 7391.03,6534.01 h65
  text "100 OHM" at 7835.59,6530.13 h65
  text "TOP" at 6579.88,6358.5 h70
  text "LAYER-3" at 8540.86,6352.26 h65
  text "4 MILS" at 6939.68,6348.49 h65
  text "5.1 MILS" at 7372.94,6346.8 h65
  text "120 OHM" at 7817.5,6342.93 h65
  text "LAYER STACK-UP :" at 3744.39,2424.42 h80
  text "Layer" at 3803.37,2272.35 h60
  text "Name" at 4213.29,2272.35 h60
  text "Material" at 5143.03,2272.35 h60
  text "Thickness" at 7122.44,2272.35 h60
  text "Constant" at 7772.27,2272.35 h60
  text "Board Layer Stack" at 8342.13,2272.35 h60
  text "Top Overlay" at 4213.29,2152.35 h60
  text "Top Solder" at 4213.29,2032.35 h60
  text "Solder Resist" at 5143.03,2032.35 h60
  text "1.00mil" at 7122.44,2032.35 h60
  text "3.5" at 7772.27,2032.35 h60
  text "1" at 3803.37,1912.35 h60
  text "Top Layer" at 4213.29,1912.35 h60
  text "1.85mil" at 7122.44,1912.35 h60
  text "Dielectric 1" at 4213.29,1792.35 h60
  text "Iteq IT180A Prepreg 106 RC71-NEW" at 5143.03,1792.35 h60
  text "1.78mil" at 7122.44,1792.35 h60
  text "3.79" at 7772.27,1792.35 h60
  text "Dielectric 2" at 4213.29,1672.35 h60
  text "Iteq IT180A Prepreg 106 RC71-NEW" at 5143.03,1672.35 h60
  text "1.78mil" at 7122.44,1672.35 h60
  text "3.79" at 7772.27,1672.35 h60
  text "2" at 3803.37,1552.35 h60
  text "L2_GND1" at 4213.29,1552.35 h60
  text "1.26mil" at 7122.44,1552.35 h60
  text "Dielectric 3" at 4213.29,1432.35 h60
  text "Iteq IT180A 50 mil core 1/1" at 5143.03,1432.35 h60
  text "47.24mil" at 7122.44,1432.35 h60
  text "4.28" at 7772.27,1432.35 h60
  text "3" at 3803.37,1312.35 h60
  text "L3_PWR1" at 4213.29,1312.35 h60
  text "1.26mil" at 7122.44,1312.35 h60
  text "Dielectric 4" at 4213.29,1192.35 h60
  text "Iteq IT180A Prepreg 106 RC71-NEW" at 5143.03,1192.35 h60
  text "1.78mil" at 7122.44,1192.35 h60
  text "3.79" at 7772.27,1192.35 h60
  text "Dielectric 5" at 4213.29,1072.35 h60
  text "Iteq IT180A Prepreg 106 RC71-NEW" at 5143.03,1072.35 h60
  text "1.78mil" at 7122.44,1072.35 h60
  text "3.79" at 7772.27,1072.35 h60
  text "4" at 3803.37,952.35 h60
  text "Bottom Layer" at 4213.29,952.35 h60
  text "1.85mil" at 7122.44,952.35 h60
  text "Bottom Solder" at 4213.29,832.35 h60
  text "Solder Resist" at 5143.03,832.35 h60
  text "1.00mil" at 7122.44,832.35 h60
  text "3.5" at 7772.27,832.35 h60
  text "Bottom Overlay" at 4213.29,712.35 h60
  text "Total board thickness:" at 3803.37,592.35 h60
  text "62.58mil" at 7122.44,592.35 h60
  text ".Layer_Name" at -126.25,-643.14 h40
M13 Component Bodies Top:
  text ".Layer_Name" at -544.88,-674.55 h60
M14 Component Bodies Bottom:
  text ".Layer_Name" at -544.88,-674.55 h60
M15 Courtyards Top:
  text ".Layer_Name" at -544.88,-674.55 h60
M16 Courtyards Bottom:
  text ".Layer_Name" at -544.88,-674.55 h60
Drill Drawing:
  drawing of 182 lines, arcs and shapes, not listed
  text "Symbol" at -619.93,7690.1 h72
  text "Count" at -114.06,7690.1 h72
  text "Hole Size" at 535.77,7690.1 h72
  text "Plated" at 1685.43,7690.1 h72
  text "Hole Length" at 2191.31,7690.1 h72
  text "Hole Tolerance" at 3340.97,7690.1 h72
  text "12" at -114.06,7540.1 h60
  text "7.87mil (0.200mm)" at 535.77,7540.1 h60
  text "PTH" at 1685.43,7540.1 h60
  text "-" at 2191.31,7540.1 h60
  text "+/-3.00mil" at 3340.97,7540.1 h60
  text "E" at -649.02,7530.11 h66.67
  text "1224" at -114.06,7390.1 h60
  text "8.00mil (0.203mm)" at 535.77,7390.1 h60
  text "PTH" at 1685.43,7390.1 h60
  text "-" at 2191.31,7390.1 h60
  text "+/-3.00mil" at 3340.97,7390.1 h60
  text "3" at -114.06,7240.1 h60
  text "23.62mil (0.600mm)" at 535.77,7240.1 h60
  text "PTH" at 1685.43,7240.1 h60
  text "-" at 2191.31,7240.1 h60
  text "+/-3.00mil" at 3340.97,7240.1 h60
  text "4" at -114.06,7090.1 h60
  text "23.62mil (0.600mm)" at 535.77,7090.1 h60
  text "PTH" at 1685.43,7090.1 h60
  text "51.18mil (1.300mm)" at 2191.31,7090.1 h60
  text "+/-3.00mil" at 3340.97,7090.1 h60
  text "2" at -114.06,6940.1 h60
  text "33.47mil (0.850mm)" at 535.77,6940.1 h60
  text "NPTH" at 1685.43,6940.1 h60
  text "-" at 2191.31,6940.1 h60
  text "+/-3.00mil" at 3340.97,6940.1 h60
  text "4" at -114.06,6790.1 h60
  text "33.47mil (0.850mm)" at 535.77,6790.1 h60
  text "PTH" at 1685.43,6790.1 h60
  text "-" at 2191.31,6790.1 h60
  text "+/-3.00mil" at 3340.97,6790.1 h60
  text "16" at -114.06,6640.1 h60
  text "39.37mil (1.000mm)" at 535.77,6640.1 h60
  text "PTH" at 1685.43,6640.1 h60
  text "-" at 2191.31,6640.1 h60
  text "+/-3.00mil" at 3340.97,6640.1 h60
  text "2" at -114.06,6490.1 h60
  text "39.37mil (1.000mm)" at 535.77,6490.1 h60
  text "PTH" at 1685.43,6490.1 h60
  text "118.11mil (3.000mm)" at 2191.31,6490.1 h60
  text "+/-3.94mil" at 3340.97,6490.1 h60
  text "1" at -114.06,6340.1 h60
  text "39.37mil (1.000mm)" at 535.77,6340.1 h60
  text "PTH" at 1685.43,6340.1 h60
  text "137.79mil (3.500mm)" at 2191.31,6340.1 h60
  text "+/-3.94mil" at 3340.97,6340.1 h60
  text "1" at -114.06,6190.1 h60
  text "40.00mil (1.016mm)" at 535.77,6190.1 h60
  text "PTH" at 1685.43,6190.1 h60
  text "-" at 2191.31,6190.1 h60
  text "+/-3.00mil" at 3340.97,6190.1 h60
  text "A" at -649.02,6180.11 h66.67
  text "2" at -114.06,6040.1 h60
  text "40.16mil (1.020mm)" at 535.77,6040.1 h60
  text "NPTH" at 1685.43,6040.1 h60
  text "-" at 2191.31,6040.1 h60
  text "+/-2.00mil" at 3340.97,6040.1 h60
  text "7" at -114.06,5890.1 h60
  text "40.16mil (1.020mm)" at 535.77,5890.1 h60
  text "PTH" at 1685.43,5890.1 h60
  text "-" at 2191.31,5890.1 h60
  text "+/-3.00mil" at 3340.97,5890.1 h60
  text "B" at -649.02,5880.11 h66.67
  text "4" at -114.06,5740.1 h60
  text "43.31mil (1.100mm)" at 535.77,5740.1 h60
  text "PTH" at 1685.43,5740.1 h60
  text "-" at 2191.31,5740.1 h60
  text "+/-3.00mil" at 3340.97,5740.1 h60
  text "6" at -114.06,5590.1 h60
  text "49.21mil (1.250mm)" at 535.77,5590.1 h60
  text "PTH" at 1685.43,5590.1 h60
  text "-" at 2191.31,5590.1 h60
  text "+/-3.00mil" at 3340.97,5590.1 h60
  text "3" at -114.06,5440.1 h60
  text "118.11mil (3.000mm)" at 535.77,5440.1 h60
  text "NPTH" at 1685.43,5440.1 h60
  text "-" at 2191.31,5440.1 h60
  text "+/-2.00mil" at 3340.97,5440.1 h60
  text "4" at -114.06,5290.1 h60
  text "118.11mil (3.000mm)" at 535.77,5290.1 h60
  text "PTH" at 1685.43,5290.1 h60
  text "-" at 2191.31,5290.1 h60
  text "+/-3.00mil" at 3340.97,5290.1 h60
  text "4" at -114.06,5140.1 h60
  text "160.00mil (4.064mm)" at 535.77,5140.1 h60
  text "NPTH" at 1685.43,5140.1 h60
  text "-" at 2191.31,5140.1 h60
  text "+/-2.00mil" at 3340.97,5140.1 h60
  text "1299 Total" at -114.06,4990.1 h60
  text "Slot definitions :" at -619.93,4845.13 h60
  text "Routed Path Length" at 412.76,4845.13 h60
  text "= Calculated from tool start centre position to tool end centre position." at 1515.42,4845.13 h60
  text "Hole Length" at 412.76,4745.16 h60
  text "= Routed Path Length + Tool Size = Slot length as defined in the PCB layout" at 1105.55,4745.16 h60
  text ".Layer_Name" at -495.55,-703.35 h60
SAMTEC CABLE:
  drawing of 5007 lines, arcs and shapes, not listed
DCA1000:
  drawing of 10999 lines, arcs and shapes, not listed
PROC074B-PCB_dxf:
  drawing of 11227 lines, arcs and shapes, not listed
3D Ficture-DXF:
  lines w0.5: 792.84,2021.55 1201.5,2021.55 ; 792.84,2021.55 792.84,3753.84 ; 792.84,2021.55 1201.5,2021.55 ; 792.84,2021.55 792.84,3753.84 ; 792.84,3753.84 2367.64,3753.84 ; 792.84,3753.84 2367.64,3753.84 ; 989.69,2375.88 989.69,3556.99 989.69,2375.88 ; 989.69,2375.88 1201.5,2375.88 ; 989.69,2375.88 1201.5,2375.88 ; 1193.11,2071.89 1193.11,2184.49 ; 1193.11,2071.89 1193.11,2184.49 ; 1193.11,2071.89 1193.11,2184.49 ; 1193.11,2071.89 1193.11,2184.49 ; 1201.5,2021.55 1958.19,2021.55 ; 1201.5,2021.55 1958.19,2021.55 ; 1201.5,2134.15 ccw(c1201.5,2193.8) 1201.5,2253.44 ; 1201.5,2134.15 cw(c1201.5,2193.8) 1201.5,2253.44 ; 1201.5,2134.15 ccw(c1201.5,2193.8) 1201.5,2253.44 ; 1201.5,2134.15 cw(c1201.5,2193.8) 1201.5,2253.44 ; 1201.5,2253.44 1201.5,2375.88 ; 1201.5,2253.44 1201.5,2375.88 ; 1201.5,2253.44 1201.5,2375.88 ; 1201.5,2253.44 1201.5,2375.88 ; 1201.5,2375.88 2170.79,2375.88 ; 1201.5,2375.88 2170.79,2375.88 ; 1958.19,2021.55 2367.64,2021.55 ; 1958.19,2021.55 1958.19,2134.15 ; 1958.19,2021.55 1958.19,2134.15 ; 1958.19,2021.55 2367.64,2021.55 ; 1958.19,2021.55 1958.19,2134.15 ; 1958.19,2021.55 1958.19,2134.15 ; 1958.19,2134.15 ccw(c1958.19,2193.8) 1958.19,2253.44 ; 1958.19,2134.15 cw(c1958.19,2193.8) 1958.19,2253.44 ; 1958.19,2134.15 ccw(c1958.19,2193.8) 1958.19,2253.44 ; 1958.19,2134.15 cw(c1958.19,2193.8) 1958.19,2253.44 ; 2170.79,2375.88 2170.79,3556.99 2170.79,2375.88 ; 2367.64,2021.55 2367.64,3753.84 ; 2367.64,2021.55 2367.64,3753.84 ; 989.69,3566.99 2170.79,3566.99 989.69,3566.99
flat radome ABS:
  lines w0.5: 1261.15,2193.8 1260.15,2182.94 1256.96,2171.84 1251.42,2161.16 1243.68,2151.62 1234.14,2143.88 1223.45,2138.34 1212.35,2135.15 1201.5,2134.15 1190.65,2135.15 1179.54,2138.34 1168.86,2143.88 1159.32,2151.62 1151.58,2161.16 1146.04,2171.84 1142.85,2182.94 1141.85,2193.8 1142.85,2204.65 1146.04,2215.75 1151.58,2226.44 1159.32,2235.97 1168.86,2243.72 1179.54,2249.26 1190.65,2252.45 1201.5,2253.44 1212.35,2252.45 1223.45,2249.26 1234.14,2243.72 1243.68,2235.97 1251.42,2226.44 1256.96,2215.75 1260.15,2204.65 1261.15,2193.8 ; 1261.15,2193.8 1898.55,2193.8 ; 1261.15,2193.8 1898.55,2193.8 ; 1898.55,2193.8 1899.54,2204.65 1902.73,2215.75 1908.27,2226.44 1916.02,2235.97 1925.55,2243.72 1936.24,2249.26 1947.34,2252.45 1958.19,2253.44 1969.05,2252.45 1980.15,2249.26 1990.83,2243.72 2000.37,2235.97 2008.12,2226.44 2013.65,2215.75 2016.84,2204.65 2017.84,2193.8 ; 1898.55,2193.8 1899.54,2182.94 1902.73,2171.84 1908.27,2161.16 1916.02,2151.62 1925.55,2143.88 1936.24,2138.34 1947.34,2135.15 1958.19,2134.15 1969.05,2135.15 1980.15,2138.34 1990.83,2143.88 2000.37,2151.62 2008.12,2161.16 2013.65,2171.84 2016.84,2182.94 2017.84,2193.8 ; 2017.84,2193.8 2269.22,2193.8 ; 2017.84,2193.8 2269.22,2193.8 ; 2269.22,2193.8 2269.22,3655.41 891.26,3655.41 891.26,2021.55 2269.22,2021.55 2269.22,2193.8

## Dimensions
3032.48,3598.78 to 3032.48,0 on M2 Board Dimensions
3032.51,3874.51 to 3032.46,-275.73 on M2 Board Dimensions
0,3874.51 to 3032.51,3874.51 on M2 Board Dimensions
3031.49,0 to 3838.42,-52.03 on M10 Fab Notes
3031.47,3598.78 to 2497.67,4206.16 on M10 Fab Notes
